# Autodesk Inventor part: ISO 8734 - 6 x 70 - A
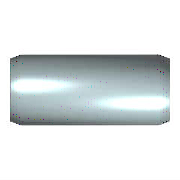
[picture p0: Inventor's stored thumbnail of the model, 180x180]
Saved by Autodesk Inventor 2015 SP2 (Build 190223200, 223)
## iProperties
IsCustomPart: 0
Created: 2012-02
Part Number: ISO 8734 - 6 x 70 - A
Material: Stahl
Description: Zylinderstift
Document SubType Name: Modeling
Standard: ISO 8734
Designer: rYan
Standards Organization: DIN
Language: de-DE
Size Designation: 6 x 70 - A
Categories: <MemberInstance><Categories><Category DisplayName="Verbindungselemente" InternalName="e4da775c-781d-43d5-af7c-5136215cf5a6" Mnemonic="FSTN"><Category DisplayNam
Density: 7.85 g/cm^3
Mass: 15.3728 g
Surface Area: 13.519 cm^2
Volume: 1.95832 cm^3
Appearance: Platte
Author: rYan
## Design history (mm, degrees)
sketch "Skizze"
  geometry: C1 r 3 at (0, 0); 1 further point
  constraints: 1 centre point, 1 coincident
  dimensions: "d1" = 6 diameter of C1 (= NND)
extrude "Körper" new body sketch "Skizze" distance "d2" = 70 (= NLG); taper "d3" = 0 deg
body "Solid1"
chamfer "Fase1" distance "d4" = 2.1 (= PHH); stored, may be unused: angle "d5" = 15 deg (= FAWI), second distance "d11" = 2.1 (= PHH)
chamfer "Fase2" distance "d8" = 2.1 (= PHH); stored, may be unused: angle "d9" = 15 deg (= FAWI), second distance "d12" = 2.1 (= PHH)
other parameters: "NND" = 6 [user parameter; used in 1 equation term], "NLG" = 70 [user parameter; used in 1 equation term], "PHH" = 2.1 [user parameter; used in 5 equation terms], "FAWI" = 15 deg [user parameter; used in 2 equation terms], "d13" = 0, "d15" = 0, "d16" = 0, "PHH2" = 2.1 (= PHH) [user parameter], "FAWI2" = 15 deg [user parameter]
